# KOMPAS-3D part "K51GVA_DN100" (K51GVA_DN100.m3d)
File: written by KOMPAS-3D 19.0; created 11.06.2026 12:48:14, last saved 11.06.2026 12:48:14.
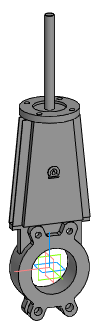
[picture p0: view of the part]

Document properties: Автор: Энергия; Полное имя файла: Z:\3.Личные\kachalov\001_3d для проектировщиков\2.6 Тип_K51GVA. Задвижка\_stp\_stp_K51GVA_DN50-DN1000_с фланцем\K51GVA_DN100.m3d

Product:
- Part/product: K51GVA_DN100

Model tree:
1. Операция без истории:1  (labels: K51GVA_DN100)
